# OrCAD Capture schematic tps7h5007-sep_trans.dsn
size Custom; title: TPS7H5007-SEP Radiation Tolerant 2-MHz; rev: *; note: Datasheet: SLVSGG1    EVM User Guide: SLVUCD8; note: Current Mode PWM Controller
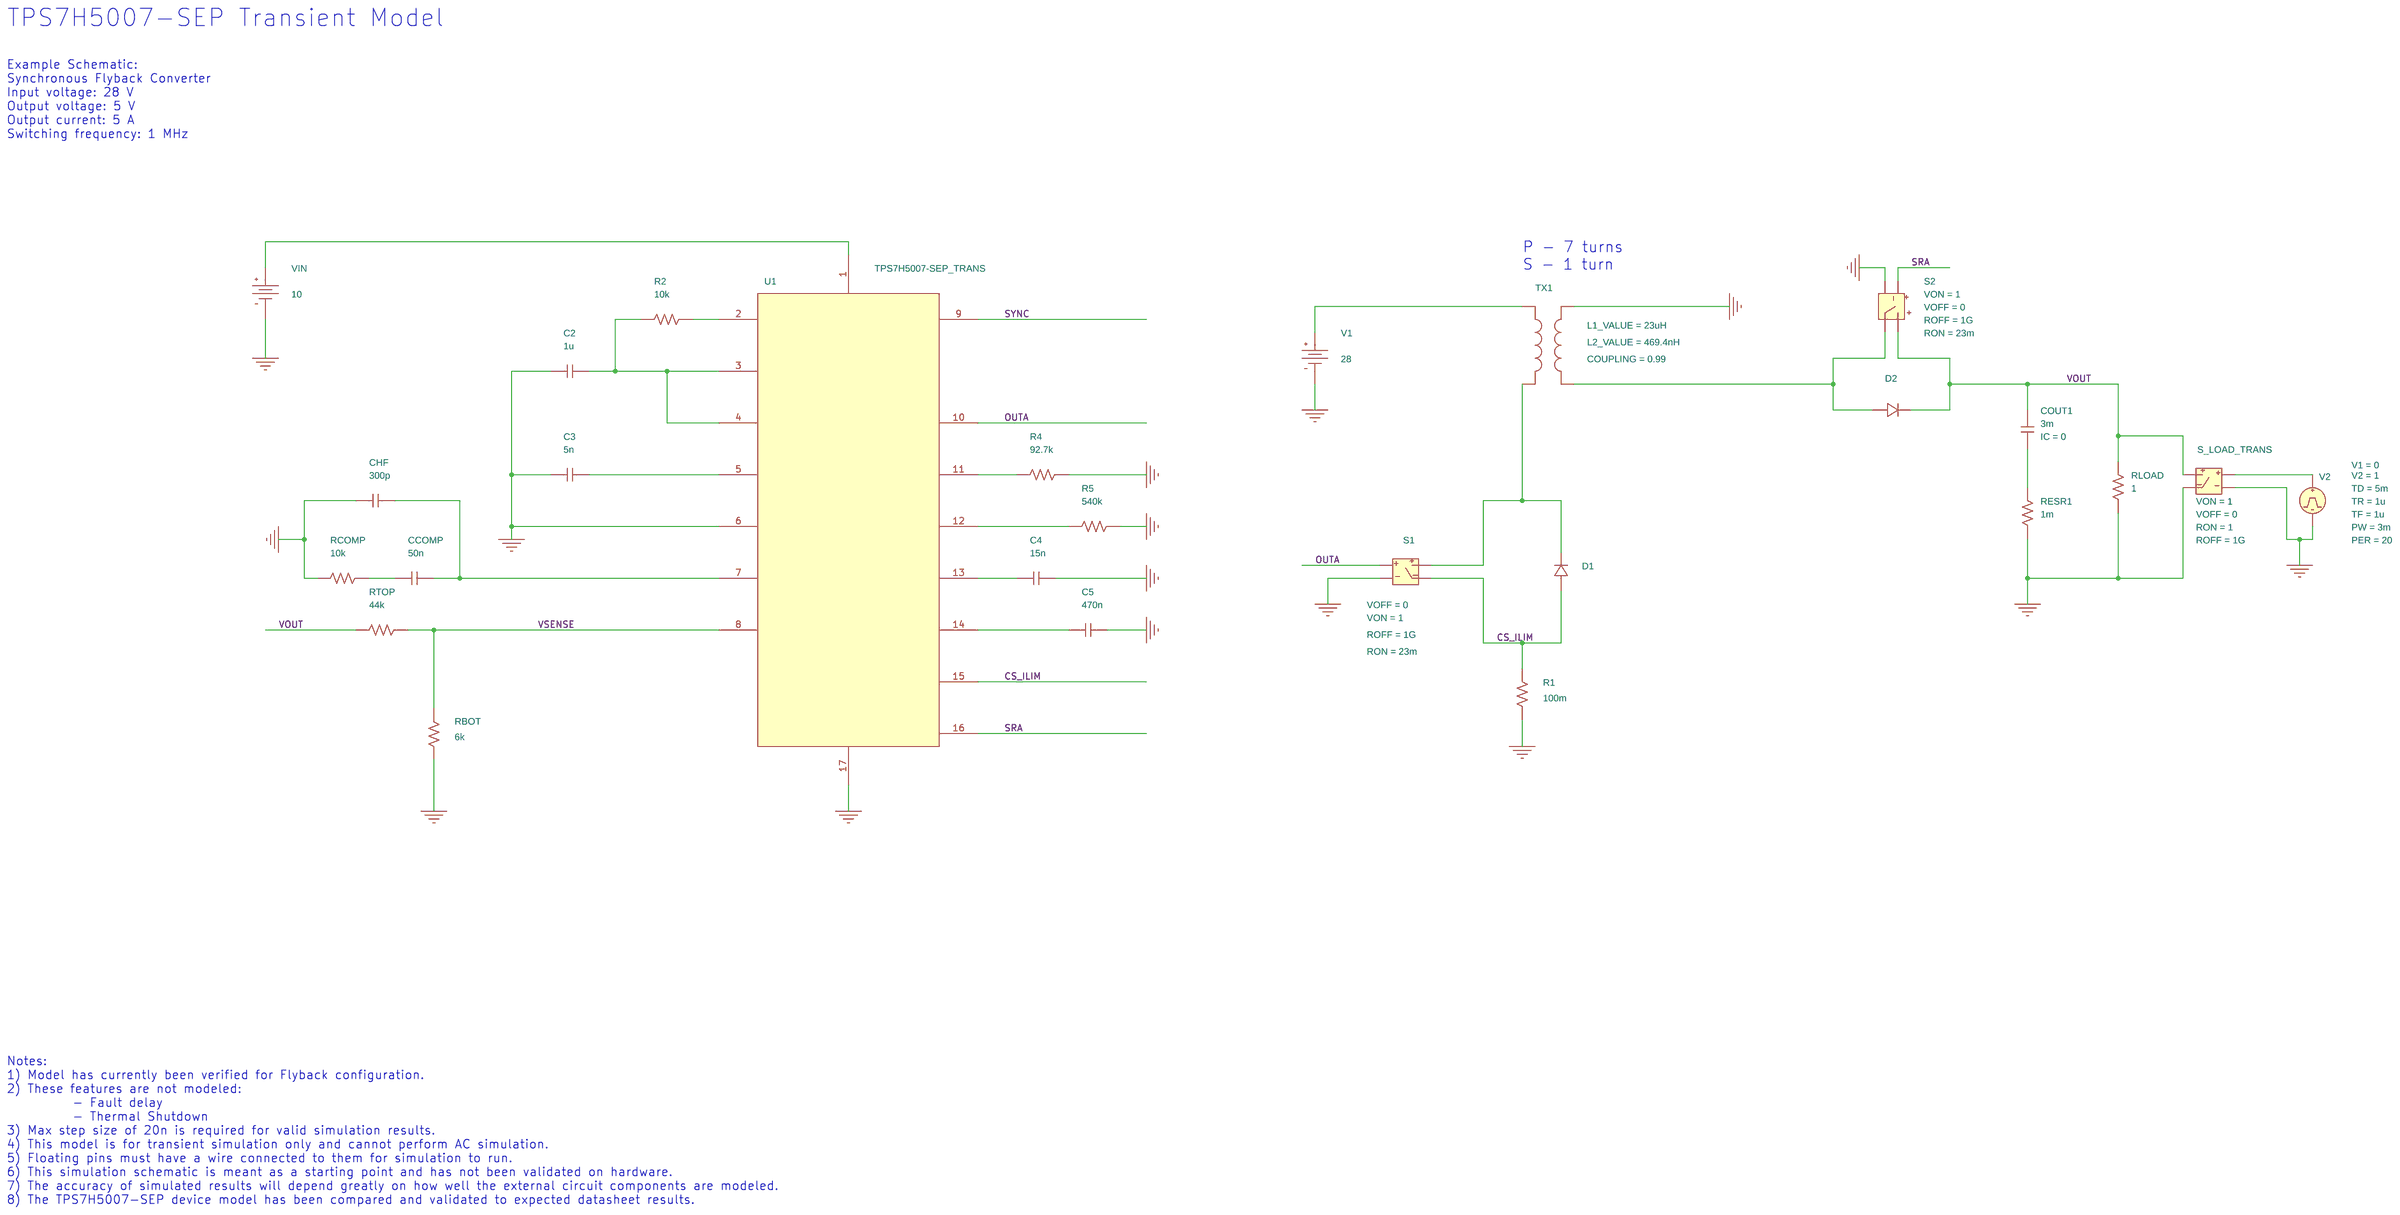
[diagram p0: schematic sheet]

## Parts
C2  1u  [cap196]
C3  5n  [cap196]
C4  15n  [cap196]
C5  470n  [cap196]
CCOMP  50n  [cap196]
CHF  300p  [cap196]
COUT1  3m  [cap196]
D1  Dbreak
D2  Dbreak
R1  100m  [AXRC05]
R2  10k  [AXRC05]
R4  92.7k  [AXRC05]
R5  540k  [AXRC05]
RBOT  6k  [AXRC05]
RCOMP  10k  [AXRC05]
RESR1  1m  [AXRC05]
RLOAD  1  [AXRC05]
RTOP  44k  [AXRC05]
S1  S
S2  S
S_LOAD_TRANS  S
TX1  XFRM_LINEAR
U1  TPS7H5007-SEP_TRANS
V1  VDC
V2  VPULSE
VIN  VDC

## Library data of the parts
C2-C5 CCOMP CHF = C
COUT1 = C: IC: 0
D1 D2 = Dbreak
R1 R2 R4 R5 RBOT RCOMP RESR1 RLOAD RTOP = R
S1 S2 = S: ROFF: 1G; RON: 23m; VOFF: 0; VON: 1
S_LOAD_TRANS = S: ROFF: 1G; RON: 1; VOFF: 0; VON: 1
TX1 = XFRM_LINEAR: COUPLING: 0.99; L1_VALUE: 23uH; L2_VALUE: 469.4nH
U1 = TPS7H5007-SEP_TRANS_0: PSpiceTemplate: X^@REFDES  %VIN %EN %VLDO %DCL %HICC %FAULT %COMP %VSENSE %SYNC %OUTA %RT %RSC %SS %REFCAP %CS_ILIM %SRA %AVSS @MODEL
V1 = VDC: DC: 28
V2 = VPULSE: PER: 20; PW: 3m; TD: 5m; TF: 1u; TR: 1u; V1: 0; V2: 1
VIN = VDC: DC: 10

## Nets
0: C2.2 C3.2 C4.1 C5.1 CHF.2 R1.1 R4.1 R5.1 RBOT.2 RCOMP.2 RESR1.1 RLOAD.1 S1.1(2) S2.1(2) S_LOAD_TRANS.1(2) S_LOAD_TRANS.3(4) TX1.3 U1.6(FAULT) U1.17(AVSS) V1.1(-) V2.2(-) VIN.1(-)
CS_ILIM: D1.0(1) R1.2 S1.3(4) U1.15(CS_ILIM)
OUTA: S1.0(1) U1.10(OUTA)
SRA: S2.0(1) U1.16(SRA)
SYNC: U1.9(SYNC)
VOUT: COUT1.2 D2.1(2) RLOAD.2 RTOP.2 S2.2(3) S_LOAD_TRANS.2(3)
VSENSE: RBOT.1 RTOP.1 U1.8(VSENSE)
N01130: U1.1(VIN) VIN.0(+)
N01272: TX1.1 V1.0(+)
N01326: C2.1 R2.2 U1.3(VLDO) U1.4(DCL)
N01334: R2.1 U1.2(EN)
N01370: D2.0(1) S2.3(4) TX1.4
N01454: D1.1(2) S1.2(3) TX1.2
N01568: COUT1.1 RESR1.2
N01668: C3.1 U1.5(HICC)
N01674: R4.2 U1.11(RT)
N01686: S_LOAD_TRANS.0(1) V2.1(+)
N01778: CCOMP.1 CHF.1 U1.7(COMP)
N01872: R5.2 U1.12(RSC)
N02064: CCOMP.2 RCOMP.1
N02080: C4.2 U1.13(SS)
N02214: C5.2 U1.14(REFCAP)

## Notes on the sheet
- TPS7H5007-SEP Transient Model
- Example Schematic:
  Synchronous Flyback Converter
  Input voltage: 28 V
  Output voltage: 5 V
  Output current: 5 A
  Switching frequency: 1 MHz
- P - 7 turns
  S - 1 turn
- Notes:
  1) Model has currently been verified for Flyback configuration.
  2) These features are not modeled:
            - Fault delay
            - Thermal Shutdown
  3) Max step size of 20n is required for valid simulation results.
  4) This model is for transient simulation only and cannot perform AC simulation.
  5) Floating pins must have a wire connected to them for simulation to run.
  6) This simulation schematic is meant as a starting point and has not been validated on hardware.
  7) The accuracy of simulated results will depend greatly on how well the external circuit components are modeled.
  8) The TPS7H5007-SEP device model has been compared and validated to expected datasheet results.
